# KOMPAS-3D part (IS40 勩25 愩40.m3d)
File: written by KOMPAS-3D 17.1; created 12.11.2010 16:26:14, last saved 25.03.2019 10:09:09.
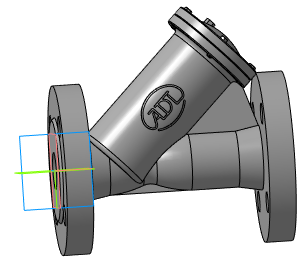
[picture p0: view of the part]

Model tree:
1. Плоскость XY
2. Плоскость ZX
3. Плоскость ZY
4. Ось X
5. Ось Y
6. Ось Z
7. Начало координат
8. Операция без истории:2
